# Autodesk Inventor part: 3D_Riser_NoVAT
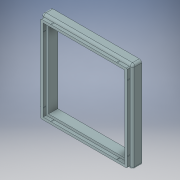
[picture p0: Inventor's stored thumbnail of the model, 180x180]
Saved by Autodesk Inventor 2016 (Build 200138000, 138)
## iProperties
Created: 2016-01
Part Number: 3D_Riser_NoVAT
Material: Generic
Document SubType Name: Modeling
Designer: John
Density: 1 g/cm^3
Appearance: Default
Author: John
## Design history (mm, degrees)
feature "SOLID1"
sketch "Sketch1"
  geometry: L1 (0, 0)-(180, 0) reference; L2 (185, 5)-(185, 185) reference; L3 (180, 190)-(0, 190) reference; L4 (-5, 185)-(-5, 5) reference; L5 (22.142, 182)-(157.858, 182) reference; L6 (174.071, 169.929)-(164.929, 179.071) reference; L7 (177, 162.858)-(177, 27.142) reference; L8 (164.929, 10.929)-(174.071, 20.071) reference; L9 (157.858, 8)-(22.142, 8) reference; L10 (5.929, 20.071)-(15.071, 10.929) reference; L11 (3, 27.142)-(3, 162.858) reference; L12 (15.071, 179.071)-(5.929, 169.929) reference; L13 (10, 175)-(170, 175); L14 (170, 175)-(170, 15); L15 (170, 15)-(10, 15); L16 (10, 15)-(10, 175); L17 (-0.114, 162.858)-(-0.114, 27.142); L18 (3.727, 17.869)-(12.869, 8.727); L19 (22.142, 4.886)-(157.858, 4.886); L20 (167.131, 8.727)-(176.273, 17.869); L21 (180.114, 27.142)-(180.114, 162.858); L22 (176.273, 172.131)-(167.131, 181.273); L23 (157.858, 185.114)-(22.142, 185.114); L24 (12.869, 181.273)-(3.727, 172.131); C1 r 1.75 at (3, 182) reference; C2 r 1.75 at (177, 8) reference; C3 r 1.75 at (177, 182) reference; C4 r 1.75 at (3, 8) reference; A1 r 5 centre (0, 5) between (-5, 5) and (0, 0) reference; A2 r 5 centre (180, 5) between (180, 0) and (185, 5) reference; A3 r 5 centre (180, 185) between (185, 185) and (180, 190) reference; A4 r 5 centre (0, 185) between (0, 190) and (-5, 185) reference; A5 r 10 centre (157.858, 172) between (164.929, 179.071) and (157.858, 182) reference; A6 r 10 centre (167, 162.858) between (177, 162.858) and (174.071, 169.929) reference; A7 r 10 centre (167, 27.142) between (174.071, 20.071) and (177, 27.142) reference; A8 r 10 centre (157.858, 18) between (157.858, 8) and (164.929, 10.929) reference; A9 r 10 centre (22.142, 18) between (15.071, 10.929) and (22.142, 8) reference; A10 r 10 centre (13, 27.142) between (3, 27.142) and (5.929, 20.071) reference; A11 r 10 centre (13, 162.858) between (5.929, 169.929) and (3, 162.858) reference; A12 r 10 centre (22.142, 172) between (22.142, 182) and (15.071, 179.071) reference; A13 r 13.114 centre (13, 162.858) between (3.727, 172.131) and (-0.114, 162.858); A14 r 13.114 centre (13, 27.142) between (-0.114, 27.142) and (3.727, 17.869); A15 r 13.114 centre (22.142, 18) between (12.869, 8.727) and (22.142, 4.886); A16 r 13.114 centre (157.858, 18) between (157.858, 4.886) and (167.131, 8.727); A17 r 13.114 centre (167, 27.142) between (176.273, 17.869) and (180.114, 27.142); A18 r 13.114 centre (167, 162.858) between (180.114, 162.858) and (176.273, 172.131); A19 r 13.114 centre (157.858, 172) between (167.131, 181.273) and (157.858, 185.114); A20 r 13.114 centre (22.142, 172) between (22.142, 185.114) and (12.869, 181.273); 5 further points
  constraints: 24 end point, 16 point on circle, 8 centre point, 4 midpoint, 2 parallel, 1 horizontal, 1 horizontal alignment, 1 perpendicular, 1 vertical alignment, 15 other
  dimensions: "d0" = 160 distance of L13.start L13.end; "d1" = 160 distance of L15.end L13.start
  node "Projected Loop1"
extrude "Extrusion1" join sketch "Sketch1" stored distance "d2" = 10; taper "d3" = 0 deg
extrude "Extrusion2" cut sketch "Sketch1" stored distance "d4" = 10; taper "d5" = 0 deg
sketch "Sketch2"
  geometry: L1 (-1.723, 180.114)-(-22.142, 180.114) reference; L2 (-22.142, 180.114)-(-22.142, 159.694) reference; L3 (-22.256, 157.972)-(-22.256, 22.256) reference; L4 (-22.142, 20.533)-(-22.142, 0.114) reference; L5 (-22.142, 0.114)-(-1.723, 0.114) reference; L6 (0, 0)-(135.716, 0) reference; L7 (137.439, 0.114)-(157.858, 0.114) reference; L8 (157.858, 0.114)-(157.858, 20.533) reference; L9 (157.972, 22.256)-(157.972, 157.972) reference; L10 (157.858, 159.694)-(157.858, 180.114) reference; L11 (157.858, 180.114)-(137.439, 180.114) reference; L12 (135.716, 180.227)-(0, 180.227) reference; L13 (147.858, 10.114)-(-12.142, 10.114) reference; L14 (-12.142, 10.114)-(-12.142, 170.114) reference; L15 (-12.142, 170.114)-(147.858, 170.114) reference; L16 (147.858, 170.114)-(147.858, 10.114) reference; L17 (-17.028, 175)-(-1.344, 175); L18 (0, 175.114)-(135.716, 175.114); L19 (137.06, 175)-(152.744, 175); L20 (152.744, 175)-(152.744, 159.315); L21 (152.858, 157.972)-(152.858, 22.256); L22 (152.744, 20.912)-(152.744, 5.227); L23 (152.744, 5.227)-(137.06, 5.227); L24 (135.716, 5.114)-(0, 5.114); L25 (-1.344, 5.227)-(-17.028, 5.227); L26 (-17.028, 5.227)-(-17.028, 20.912); L27 (-17.142, 22.256)-(-17.142, 157.972); L28 (-17.028, 159.315)-(-17.028, 175); A1 r 13.114 centre (-9.142, 157.972) between (-22.142, 159.694) and (-22.256, 157.972) reference; A2 r 13.114 centre (-9.142, 22.256) between (-22.256, 22.256) and (-22.142, 20.533) reference; A3 r 13.114 centre (0, 13.114) between (-1.723, 0.114) and (0, 0) reference; A4 r 13.114 centre (135.716, 13.114) between (135.716, 0) and (137.439, 0.114) reference; A5 r 13.114 centre (144.858, 22.256) between (157.858, 20.533) and (157.972, 22.256) reference; A6 r 13.114 centre (144.858, 157.972) between (157.972, 157.972) and (157.858, 159.694) reference; A7 r 13.114 centre (135.716, 167.114) between (137.439, 180.114) and (135.716, 180.227) reference; A8 r 13.114 centre (0, 167.114) between (0, 180.227) and (-1.723, 180.114) reference; A9 r 8 centre (0, 167.114) between (0, 175.114) and (-1.344, 175); A10 r 8 centre (135.716, 167.114) between (137.06, 175) and (135.716, 175.114); A11 r 8 centre (144.858, 157.972) between (152.858, 157.972) and (152.744, 159.315); A12 r 8 centre (144.858, 22.256) between (152.744, 20.912) and (152.858, 22.256); A13 r 8 centre (135.716, 13.114) between (135.716, 5.114) and (137.06, 5.227); A14 r 8 centre (0, 13.114) between (-1.344, 5.227) and (0, 5.114); A15 r 8 centre (-9.142, 22.256) between (-17.142, 22.256) and (-17.028, 20.912); A16 r 8 centre (-9.142, 157.972) between (-17.028, 159.315) and (-17.142, 157.972); 1 further point
  constraints: 24 end point, 16 point on circle, 8 centre point, 19 other
  dimensions: "d6" = 170 distance between parallel lines of L21 L27
extrude "Extrusion3" join sketch "Sketch2" distance "d7" = 6.35; taper "d8" = 0 deg
fillet "Fillet1" dims "d9" = 2
body "Solid1"
node "Projected Loop2"
